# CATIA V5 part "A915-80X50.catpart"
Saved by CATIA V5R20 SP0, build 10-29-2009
Part number: A915-80X50
Source: Unknown
Property "A": "30.000"
Property "ARTICLENO": "A915-80X50"
Property "BOMINFO": "A915-80X50"
Property "CODE": "A915-80X50"
Property "CREATOR": "CADENAS GmbH"
Property "D": "9.000"
Property "D1": "15.000"
Property "FORM": "A"
Property "L": "50.000"
Property "L1": "25.000"
Property "L2": "0.000"
Property "LINA": "A915-80X50"
Property "NB": "A915-80X50"
Property "NBSYN": "$CODE."
Property "NN": "A915"
Property "NT": "VDI 3357 Wear Plates, steel"
Property "SCREW": "M8x25"
Property "SUPPLIER": "CF"
Property "T": "9.000"
Property "W": "80.000"
Bounding box of the stored display mesh (mm): x 0 to 20, y 0 to 50, z -40 to 40
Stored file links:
  C:\Users\borellobunino\Desktop\3D X SITO CF\A915\GSB_OILLESS_G22501080050\A915-80X50.catpart
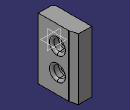
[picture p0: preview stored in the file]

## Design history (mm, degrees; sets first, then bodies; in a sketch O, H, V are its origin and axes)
Body1 "Geometry.1" (main body)
  Solid1 "A915-80X50.catpart": solid without history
